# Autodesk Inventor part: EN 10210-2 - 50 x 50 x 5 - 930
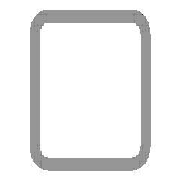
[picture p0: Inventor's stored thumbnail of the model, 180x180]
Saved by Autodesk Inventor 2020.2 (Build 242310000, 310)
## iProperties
IsCustomPart: 1
_CCFamilyMember: 16
_CCFamilyDisplayName: DIN EN 10210-2 (USAS B17.1 quadratisch) - Rohrleitung — In Klammern angegebene Größen wurden aufgehoben
_FrameMemberDoc: Frame Member File
_Version: 15.0.0
_GetPNFromCC: 1
Created: 2019-10
Part Number: EN 10210-2 - 50 x 50 x 5 - 930
Material: Stahl, weich
Description: Rohrleitung
Document SubType Name: Modeling
Standard: DIN
Designer: lutzd
Standard Revision: 2006-07
Standards Organization: DIN
Language: de-DE
Size Designation: 50 x 50 x 5
Categories: <MemberInstance><Categories><Category DisplayName="Profile" InternalName="089c4875-fa83-4c05-b084-43b9cc11f5ed" Mnemonic="GRDR"><CategoryParameter DisplayName="
Stock Number: 50 x 50 x 5
Mass: 6374.61 g
Surface Area: 3165.88 cm^2
Volume: 812.053 cm^3
Density: 7.85 g/cm^3
Appearance: Semi-Polished(8)
G_L: 930,000 mm
G_W: 50,000 mm
G_H: 50,000 mm
Dimensions: 50x50x930 mm
Mass: 6,375 kg
DocNumber: ADSK-014300
Folder: .
+584A277F-9A3A-4FEF-97B7-81D94234EAB9+SCHNITTDETAIL1: Schnittwinkel 90,00 grd
+BA5D7D3B-783A-4418-8A14-B2D4A9E1C962+SCHNITTDETAIL2: Schnittwinkel 90,00 grd
VLT_Material: Stahl, weich
Title: Profil-Bauteil
Author: lutzd
Revision Number: -
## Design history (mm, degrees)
node "Startebene"
node "Endebene"
sketch "Skizze"
  geometry: L1 (-25, -17.5)-(-25, 17.5); L2 (-17.5, 25)-(17.5, 25); L3 (25, 17.5)-(25, -17.5); L4 (17.5, -25)-(-17.5, -25); L5 (-15, 20)-(15, 20); L6 (20, 15)-(20, -15); L7 (15, -20)-(-15, -20); L8 (-20, -15)-(-20, 15); L9 (0, 37.175)-(0, -37.175) reference; L10 (-37.175, 0)-(37.175, 0) reference; A1 r 7.5 centre (-17.5, -17.5) between (-25, -17.5) and (-17.5, -25); A2 r 7.5 centre (-17.5, 17.5) between (-17.5, 25) and (-25, 17.5); A3 r 7.5 centre (17.5, 17.5) between (25, 17.5) and (17.5, 25); A4 r 7.5 centre (17.5, -17.5) between (17.5, -25) and (25, -17.5); A5 r 5 centre (-15, -15) between (-20, -15) and (-15, -20); A6 r 5 centre (-15, 15) between (-15, 20) and (-20, 15); A7 r 5 centre (15, 15) between (20, 15) and (15, 20); A8 r 5 centre (15, -15) between (15, -20) and (20, -15)
  constraints: 16 end point, 16 point on circle, 16 tangent, 8 centre point, 6 equal radius, 4 parallel, 2 perpendicular, 2 other
  dimensions: "d7" = 7.5 radius of A1 (= G_IR); "d10" = 50 distance between parallel lines of L2 L4 (= G_H); "d11" = 50 distance between parallel lines of L1 L3 (= G_W); "d12" = 5 distance between parallel lines of L3 L6 (= G_T); "d15" = 25 distance between parallel lines of L2 L10 (= 0.5 x d10); "d16" = 25 distance between parallel lines of L9 L3 (= 0.5 x d11); "d19" = 5 radius of A5 (= G_T); "d20" = 5 distance between parallel lines of L4 L7 (= G_T)
extrude "Körper" new body sketch "Skizze" stored distance "d3" = 930 (= G_L); taper "d4" = 0 deg
node "Driven Length"
  sketch "Sketch3"
    geometry: L1 (0, 0)-(10, 0) reference
    constraints: 2 end point, 1 horizontal
  workplane "Work Plane3"
  sketch "Sketch4"
    geometry: L1 (-2, 50)-(12, 50) reference; L2 (-2, 980)-(12, 980) reference
    dimensions: "d18" = 930 distance between parallel lines of L1 L2 (derived)
workplane "Arbeitsebene4"
feature "Trennen1"
workplane "Arbeitsebene5"
feature "Trennen2"
body "Solid1"
other parameters: "G_W" = 50 [user parameter; used in 1 equation term], "G_H" = 50 [user parameter; used in 1 equation term], "G_T" = 5 [user parameter; used in 3 equation terms], "G_IR" = 7.5 [user parameter; used in 1 equation term], "G_L" = 930 (= d18) [user parameter; used in 1 equation term], "d17" = 90 deg
